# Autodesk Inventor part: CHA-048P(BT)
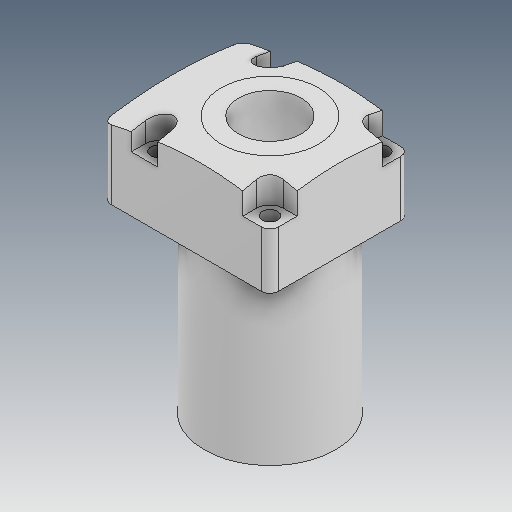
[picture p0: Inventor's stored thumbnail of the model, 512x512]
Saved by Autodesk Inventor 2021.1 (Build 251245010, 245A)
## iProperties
Created: 2021-05
Part Number: CHA-048P(BT)
Material: Ogólny
Document SubType Name: Modeling
Designer: user
Density: 1 g/cm^3
Appearance: Domyślna
Author: user
Revision Number: ÈÎºÎ
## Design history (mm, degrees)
feature "¾µÏò1"
node "Bryła1"
